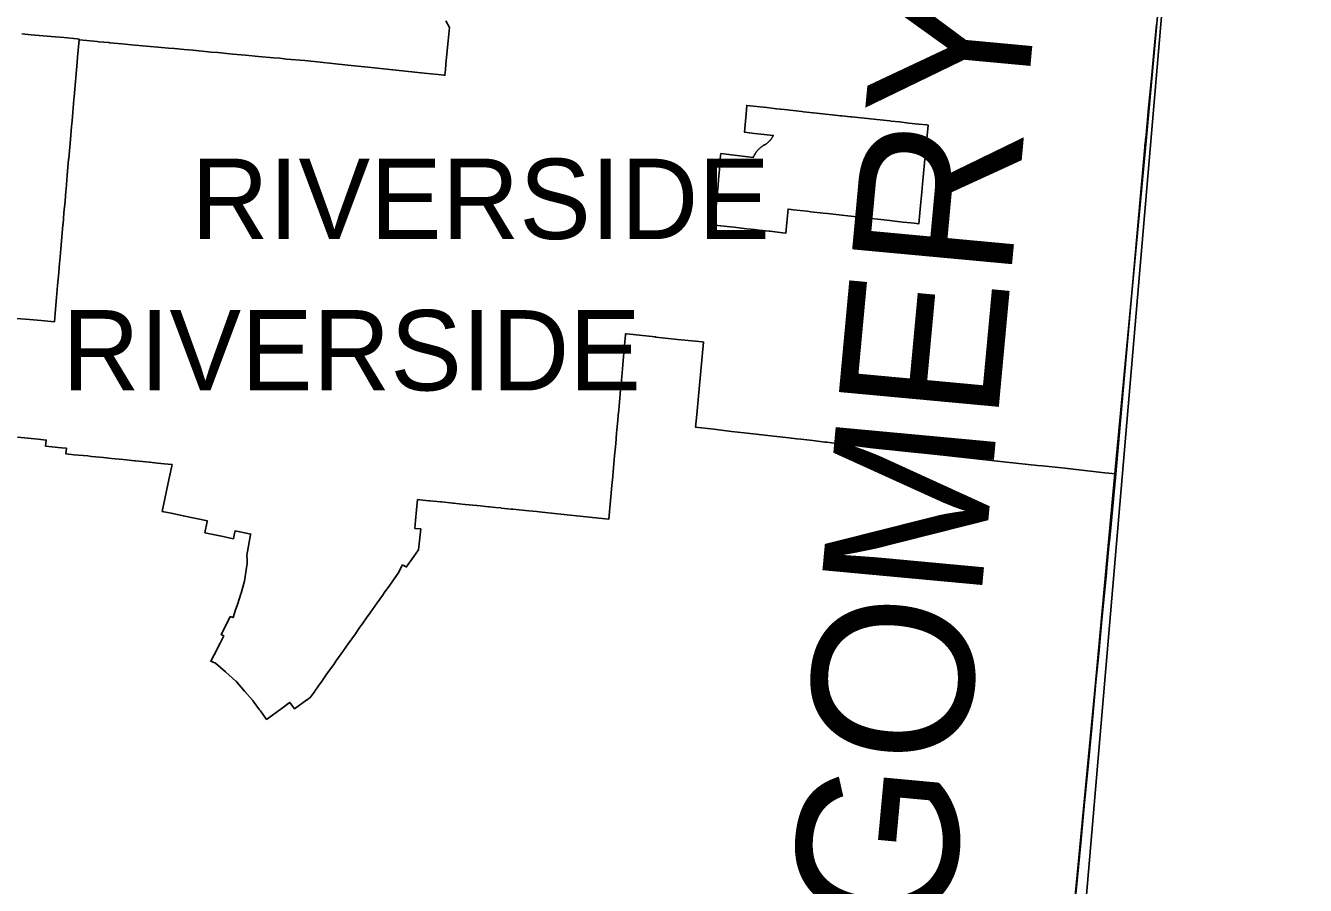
# Model space of a CAD drawing. Extents: x 0 to 34, y 0 to 22.
# Drawn here: x 5.6354 to 5.7635, y 15.4621 to 15.5481 of the extents above; entities that cross this region are included whole.
import ezdxf

# ---------------------------------------------------------------- set-up
doc = ezdxf.new("R2010")
doc.units = 0
for name, color, linetype in [('GM_X_Corporation', 7, 'Continuous'), ('GM_X_Corporation_Text', 7, 'Continuous'), ('GM_X_County', 7, 'Continuous'), ('GM_X_County_Text', 7, 'Continuous'), ('SC_Scratch1', 7, 'Continuous')]:
    doc.layers.add(name, color=color, linetype=linetype)

msp = doc.modelspace()

# ---------------------------------------------------------------- linework, layer by layer
at = {"layer": 'GM_X_Corporation'}
for points in [[(5.63452, 15.51883), (5.63582, 15.51872), (5.637, 15.51861), (5.63832, 15.51849), (5.63843, 15.51974), (5.63854, 15.52092), (5.63864, 15.52213), (5.63875, 15.52341), (5.63884, 15.5244), (5.63886, 15.52458), (5.63896, 15.52579), (5.63906, 15.52697), (5.63917, 15.52818), (5.63918, 15.52826), (5.63927, 15.52939), (5.63938, 15.53056), (5.63946, 15.53156), (5.63948, 15.53177), (5.63961, 15.53317), (5.63974, 15.53471), (5.63975, 15.53484), (5.63992, 15.53674), (5.64003, 15.53802), (5.64008, 15.5386), (5.64026, 15.54073), (5.64029, 15.54098), (5.64059, 15.54446), (5.64063, 15.54496), (5.64079, 15.5467), (5.64157, 15.54663), (5.64259, 15.54653), (5.64278, 15.54651), (5.64377, 15.54642), (5.64387, 15.54641), (5.64508, 15.5463), (5.64636, 15.54618), (5.64754, 15.54608), (5.64905, 15.54594), (5.64974, 15.54587), (5.65035, 15.54582), (5.65132, 15.54573), (5.65218, 15.54565), (5.65402, 15.54548), (5.65467, 15.54542), (5.65618, 15.54528), (5.65746, 15.54516), (5.65874, 15.54504), (5.66025, 15.5449), (5.66087, 15.54485), (5.66156, 15.54478), (5.66338, 15.54462), (5.66768, 15.54417), (5.67003, 15.54392), (5.67533, 15.54337), (5.67672, 15.54323), (5.67731, 15.54317), (5.67732, 15.54317), (5.67741, 15.54316), (5.67746, 15.54369), (5.67746, 15.54372), (5.67746, 15.54378), (5.67751, 15.5442), (5.67751, 15.54428), (5.67764, 15.54562), (5.67774, 15.54661), (5.67783, 15.54761), (5.67787, 15.54794), (5.67751, 15.5486)], [(5.74863, 15.54822), (5.74847, 15.54651), (5.74834, 15.54508), (5.74812, 15.54284), (5.74784, 15.53988), (5.74759, 15.53716), (5.74754, 15.5367), (5.74753, 15.5366), (5.74747, 15.53612), (5.74746, 15.53596), (5.74529, 15.51163), (5.74455, 15.50327), (5.74453, 15.50328), (5.74346, 15.50339), (5.73915, 15.50386), (5.73719, 15.50407), (5.73671, 15.50412), (5.73362, 15.50445), (5.73002, 15.50484), (5.72792, 15.50507), (5.72638, 15.50523), (5.72278, 15.50562), (5.72223, 15.50569), (5.71961, 15.50598), (5.71919, 15.50603), (5.71864, 15.50609), (5.71782, 15.50619), (5.71662, 15.50632), (5.71563, 15.50644), (5.71543, 15.50646), (5.71423, 15.5066), (5.71303, 15.50673), (5.71261, 15.50678), (5.7121, 15.50684), (5.71183, 15.50687), (5.71064, 15.50701), (5.70944, 15.50714), (5.70796, 15.50731), (5.70734, 15.50738), (5.7061, 15.50752), (5.70432, 15.50773), (5.7025, 15.50793), (5.70261, 15.50921), (5.70289, 15.51216), (5.70329, 15.51645), (5.70314, 15.51647), (5.70249, 15.51654), (5.70068, 15.51673), (5.69946, 15.51686), (5.69851, 15.51696), (5.69845, 15.51697), (5.69689, 15.51714), (5.69591, 15.51724), (5.69558, 15.51728), (5.69548, 15.51729), (5.69547, 15.51719), (5.69535, 15.51579), (5.69528, 15.51499), (5.69513, 15.51338), (5.6951, 15.51299), (5.6951, 15.51297), (5.69498, 15.5117), (5.69487, 15.51043), (5.6948, 15.50966), (5.69475, 15.50916), (5.69471, 15.50864), (5.69462, 15.50768), (5.69459, 15.50734), (5.6945, 15.5063), (5.69444, 15.50568), (5.69439, 15.50507), (5.69425, 15.50351), (5.69421, 15.50305), (5.6942, 15.50301), (5.69412, 15.50211), (5.69382, 15.49875), (5.69313, 15.49882), (5.68868, 15.49928), (5.68685, 15.49947), (5.6866, 15.49949), (5.6858, 15.49957), (5.6842, 15.49973), (5.68403, 15.49975), (5.68302, 15.49985), (5.683, 15.49986), (5.68246, 15.49991), (5.68185, 15.49997), (5.6818, 15.49998), (5.68064, 15.5001), (5.6806, 15.5001), (5.67943, 15.50022), (5.6794, 15.50022), (5.67826, 15.50034), (5.6782, 15.50034), (5.67708, 15.50046), (5.677, 15.50047), (5.67588, 15.50058), (5.6758, 15.50059), (5.67488, 15.50068), (5.67467, 15.5007), (5.67456, 15.49968), (5.67446, 15.49862), (5.67438, 15.49782), (5.67498, 15.49776), (5.67477, 15.49568), (5.67429, 15.495), (5.67354, 15.49394), (5.67349, 15.49397), (5.67345, 15.494), (5.6734, 15.49403), (5.67337, 15.49405), (5.67335, 15.49406), (5.6733, 15.49409), (5.67325, 15.49412), (5.67317, 15.49416), (5.67297, 15.49379), (5.6728, 15.49345), (5.67188, 15.49215), (5.67133, 15.49137), (5.67114, 15.4911), (5.67063, 15.49038), (5.6704, 15.49005), (5.66993, 15.48938), (5.66957, 15.48887), (5.66919, 15.48833), (5.66882, 15.48782), (5.66855, 15.48744), (5.66844, 15.48728), (5.66808, 15.48677), (5.66773, 15.48627), (5.66725, 15.48559), (5.66701, 15.48526), (5.6665, 15.48454), (5.66627, 15.48421), (5.66576, 15.48349), (5.66553, 15.48316), (5.66504, 15.48247), (5.66483, 15.48217), (5.66432, 15.48144), (5.66394, 15.48092), (5.6636, 15.48067), (5.66358, 15.48065), (5.66236, 15.47976), (5.66189, 15.48041), (5.66153, 15.48015), (5.66152, 15.48014), (5.66124, 15.47994), (5.65955, 15.47871), (5.65894, 15.47955), (5.65885, 15.47966), (5.65822, 15.48054), (5.65817, 15.4806), (5.65813, 15.48064), (5.65738, 15.48151), (5.65737, 15.48152), (5.65736, 15.48154), (5.65661, 15.4824), (5.65651, 15.48252), (5.65649, 15.48254), (5.65577, 15.48317), (5.65548, 15.48342), (5.65544, 15.48346), (5.65493, 15.48391), (5.65445, 15.48433), (5.65397, 15.48454), (5.6543, 15.48518), (5.6549, 15.48634), (5.65503, 15.4866), (5.65527, 15.48705), (5.65514, 15.48712), (5.65501, 15.48718), (5.65591, 15.489), (5.6562, 15.48889), (5.65645, 15.48966), (5.6566, 15.49011), (5.65687, 15.49093), (5.65698, 15.49127), (5.657, 15.49133), (5.65729, 15.49231), (5.65736, 15.49254), (5.65752, 15.49366), (5.6576, 15.49432), (5.6576, 15.49467), (5.6576, 15.49472), (5.65759, 15.49513), (5.65796, 15.49717), (5.65798, 15.49725), (5.6564, 15.49757), (5.65631, 15.49713), (5.65624, 15.49681), (5.65623, 15.49678), (5.65546, 15.49694), (5.65522, 15.49699), (5.65338, 15.49738), (5.65361, 15.49849), (5.65363, 15.49858), (5.65122, 15.49908), (5.65016, 15.49929), (5.64911, 15.49951), (5.64981, 15.50284), (5.6501, 15.5042), (5.64929, 15.50428), (5.64862, 15.50435), (5.64782, 15.50443), (5.64781, 15.50443), (5.64645, 15.50457), (5.64637, 15.50458), (5.64519, 15.5047), (5.6444, 15.50478), (5.64402, 15.50482), (5.64323, 15.5049), (5.64284, 15.50494), (5.64202, 15.50502), (5.64167, 15.50506), (5.64074, 15.50515), (5.64031, 15.50519), (5.63946, 15.50528), (5.63952, 15.50584), (5.63904, 15.50589), (5.63744, 15.50605), (5.6375, 15.50665), (5.6367, 15.50673), (5.63462, 15.50694)], [(5.67751, 15.5486), (5.67787, 15.54794), (5.67783, 15.54761), (5.67774, 15.54661), (5.67764, 15.54562), (5.67751, 15.54428), (5.67751, 15.5442), (5.67746, 15.54378), (5.67746, 15.54372), (5.67746, 15.54369), (5.67741, 15.54316), (5.67732, 15.54317), (5.67731, 15.54317), (5.67672, 15.54323), (5.67533, 15.54337), (5.67003, 15.54392), (5.66768, 15.54417), (5.66338, 15.54462), (5.66156, 15.54478), (5.66087, 15.54485), (5.66025, 15.5449), (5.65874, 15.54504), (5.65746, 15.54516), (5.65618, 15.54528), (5.65467, 15.54542), (5.65402, 15.54548), (5.65218, 15.54565), (5.65132, 15.54573), (5.65035, 15.54582), (5.64974, 15.54587), (5.64905, 15.54594), (5.64754, 15.54608), (5.64636, 15.54618), (5.64508, 15.5463), (5.64387, 15.54641), (5.64377, 15.54642), (5.64278, 15.54651), (5.64259, 15.54653), (5.64157, 15.54663), (5.64079, 15.5467), (5.64079, 15.54678), (5.6406, 15.5468), (5.6393, 15.54692), (5.63839, 15.547), (5.63599, 15.54721), (5.63505, 15.54729)], [(5.63505, 15.54729), (5.63599, 15.54721), (5.63839, 15.547), (5.6393, 15.54692), (5.6406, 15.5468), (5.64079, 15.54678), (5.64079, 15.5467), (5.64063, 15.54496), (5.64059, 15.54446), (5.64029, 15.54098), (5.6403, 15.54098), (5.64026, 15.54073), (5.64008, 15.5386), (5.64003, 15.53802), (5.63992, 15.53674), (5.63975, 15.53484), (5.63974, 15.53471), (5.63961, 15.53317), (5.63948, 15.53177), (5.63946, 15.53156), (5.63938, 15.53056), (5.63927, 15.52939), (5.63918, 15.52826), (5.63917, 15.52818), (5.63906, 15.52697), (5.63896, 15.52579), (5.63886, 15.52458), (5.63884, 15.5244), (5.63875, 15.52341), (5.63864, 15.52213), (5.63854, 15.52092), (5.63843, 15.51974), (5.63832, 15.51849), (5.637, 15.51861), (5.63582, 15.51872), (5.63452, 15.51883)], [(5.63462, 15.50694), (5.6367, 15.50673), (5.6375, 15.50665), (5.63744, 15.50605), (5.63904, 15.50589), (5.63952, 15.50584), (5.63946, 15.50528), (5.64031, 15.50519), (5.64074, 15.50515), (5.64167, 15.50506), (5.64202, 15.50502), (5.64284, 15.50494), (5.64323, 15.5049), (5.64402, 15.50482), (5.6444, 15.50478), (5.64519, 15.5047), (5.64637, 15.50458), (5.64645, 15.50457), (5.64782, 15.50443), (5.64862, 15.50435), (5.64929, 15.50428), (5.6501, 15.5042), (5.64981, 15.50284), (5.64911, 15.49951), (5.65016, 15.49929), (5.65122, 15.49908), (5.65363, 15.49858), (5.65361, 15.49849), (5.65338, 15.49738), (5.65522, 15.49699), (5.65546, 15.49694), (5.65623, 15.49678), (5.65624, 15.49681), (5.65631, 15.49713), (5.6564, 15.49757), (5.65798, 15.49725), (5.65796, 15.49717), (5.65759, 15.49513), (5.6576, 15.49472), (5.6576, 15.49467), (5.6576, 15.49432), (5.65752, 15.49366), (5.65736, 15.49254), (5.65729, 15.49231), (5.657, 15.49133), (5.65698, 15.49127), (5.65687, 15.49093), (5.6566, 15.49011), (5.65645, 15.48966), (5.6562, 15.48889), (5.65591, 15.489), (5.65501, 15.48718), (5.65514, 15.48712), (5.65527, 15.48705), (5.65503, 15.4866), (5.6549, 15.48634), (5.6543, 15.48518), (5.65397, 15.48454), (5.65445, 15.48433), (5.65493, 15.48391), (5.65544, 15.48346), (5.65548, 15.48342), (5.65577, 15.48317), (5.65649, 15.48254), (5.65651, 15.48252), (5.65661, 15.4824), (5.65736, 15.48154), (5.65738, 15.48151), (5.65813, 15.48064), (5.65817, 15.4806), (5.65822, 15.48054), (5.65885, 15.47966), (5.65894, 15.47955), (5.65955, 15.47871), (5.66124, 15.47994), (5.66152, 15.48014), (5.66189, 15.48041), (5.66236, 15.47976), (5.66358, 15.48065), (5.6636, 15.48067), (5.66394, 15.48092), (5.66432, 15.48144), (5.66483, 15.48217), (5.66504, 15.48247), (5.66553, 15.48316), (5.66576, 15.48349), (5.66627, 15.48421), (5.6665, 15.48454), (5.66701, 15.48526), (5.66725, 15.48559), (5.66773, 15.48627), (5.66808, 15.48677), (5.66844, 15.48728), (5.66855, 15.48744), (5.66882, 15.48782), (5.66919, 15.48833), (5.66957, 15.48887), (5.66993, 15.48938), (5.6704, 15.49005), (5.67063, 15.49038), (5.67114, 15.4911), (5.67133, 15.49137), (5.67188, 15.49215), (5.6728, 15.49345), (5.67297, 15.49379), (5.67317, 15.49416), (5.67325, 15.49412), (5.6733, 15.49409), (5.67335, 15.49406), (5.67337, 15.49405), (5.6734, 15.49403), (5.67345, 15.494), (5.67349, 15.49397), (5.67354, 15.49394), (5.67429, 15.495), (5.67477, 15.49568), (5.67498, 15.49776), (5.67438, 15.49782), (5.67446, 15.49862), (5.67456, 15.49968), (5.67467, 15.5007), (5.67488, 15.50068), (5.6758, 15.50059), (5.67588, 15.50058), (5.677, 15.50047), (5.67708, 15.50046), (5.6782, 15.50034), (5.67826, 15.50034), (5.6794, 15.50022), (5.67943, 15.50022), (5.6806, 15.5001), (5.68064, 15.5001), (5.6818, 15.49998), (5.68185, 15.49997), (5.68246, 15.49991), (5.683, 15.49986), (5.68302, 15.49985), (5.68403, 15.49975), (5.6842, 15.49973), (5.6858, 15.49957), (5.6866, 15.49949), (5.68685, 15.49947), (5.68868, 15.49928), (5.69313, 15.49882), (5.69382, 15.49875), (5.69412, 15.50211), (5.6942, 15.50301), (5.69421, 15.50305), (5.69425, 15.50351), (5.69439, 15.50507), (5.69444, 15.50568), (5.6945, 15.5063), (5.69459, 15.50734), (5.69462, 15.50768), (5.69471, 15.50864), (5.69475, 15.50916), (5.6948, 15.50966), (5.69487, 15.51043), (5.69498, 15.5117), (5.6951, 15.51297), (5.6951, 15.51299), (5.69513, 15.51338), (5.69528, 15.51499), (5.69535, 15.51579), (5.69547, 15.51719), (5.69548, 15.51729), (5.69558, 15.51728), (5.69591, 15.51724), (5.69689, 15.51714), (5.69845, 15.51697), (5.69851, 15.51696), (5.69946, 15.51686), (5.70068, 15.51673), (5.70249, 15.51654), (5.70314, 15.51647), (5.70329, 15.51645), (5.70289, 15.51216), (5.70261, 15.50921), (5.7025, 15.50793), (5.70432, 15.50773), (5.7061, 15.50752), (5.70734, 15.50738), (5.70796, 15.50731), (5.70944, 15.50714), (5.71064, 15.50701), (5.71183, 15.50687), (5.7121, 15.50684), (5.71261, 15.50678), (5.71303, 15.50673), (5.71423, 15.5066), (5.71543, 15.50646), (5.71563, 15.50644), (5.71662, 15.50632), (5.71782, 15.50619), (5.71864, 15.50609), (5.71919, 15.50603), (5.71961, 15.50598), (5.72223, 15.50569), (5.72278, 15.50562), (5.72638, 15.50523), (5.72792, 15.50507), (5.73002, 15.50484), (5.73362, 15.50445), (5.73671, 15.50412), (5.73719, 15.50407), (5.73915, 15.50386), (5.74346, 15.50339), (5.74455, 15.50327), (5.74394, 15.49684), (5.74386, 15.49606), (5.74365, 15.49386), (5.74361, 15.49338), (5.74322, 15.48934), (5.74313, 15.48834), (5.74284, 15.48531), (5.74278, 15.48464), (5.7426, 15.48275), (5.74253, 15.48205), (5.74246, 15.4813), (5.74214, 15.4779), (5.74174, 15.47368), (5.74139, 15.47003), (5.74104, 15.46634), (5.74068, 15.46258), (5.74033, 15.45891)]]:
    msp.add_lwpolyline(points, dxfattribs=at)
for points in [[(5.70739, 15.53745), (5.70755, 15.53929), (5.70762, 15.54014), (5.70861, 15.54003), (5.70961, 15.53992), (5.7106, 15.53981), (5.71097, 15.53977), (5.7114, 15.53972), (5.71313, 15.53953), (5.7133, 15.53951), (5.71426, 15.53941), (5.71522, 15.5393), (5.7155, 15.53927), (5.71617, 15.5392), (5.71699, 15.53911), (5.71713, 15.53909), (5.718, 15.539), (5.71809, 15.53899), (5.71905, 15.53889), (5.72001, 15.53878), (5.72097, 15.53868), (5.72193, 15.53858), (5.72207, 15.53856), (5.72289, 15.53848), (5.72385, 15.53837), (5.72481, 15.53827), (5.72565, 15.53818), (5.72577, 15.53817), (5.72551, 15.53547), (5.72521, 15.53225), (5.72513, 15.53145), (5.72501, 15.53011), (5.72484, 15.52829), (5.72436, 15.52834), (5.72404, 15.52838), (5.72324, 15.52846), (5.72218, 15.52858), (5.72192, 15.52861), (5.72164, 15.52864), (5.72072, 15.52875), (5.72004, 15.52882), (5.71953, 15.52888), (5.71845, 15.529), (5.71833, 15.52902), (5.71713, 15.52915), (5.71685, 15.52918), (5.71569, 15.52931), (5.71525, 15.52936), (5.71402, 15.5295), (5.71365, 15.52954), (5.71226, 15.5297), (5.71206, 15.52972), (5.71175, 15.52976), (5.71163, 15.52841), (5.71153, 15.52736), (5.71121, 15.52739), (5.70993, 15.52754), (5.70986, 15.52754), (5.70885, 15.52766), (5.70838, 15.52771), (5.70802, 15.52775), (5.70758, 15.5278), (5.70637, 15.52794), (5.70598, 15.52798), (5.70439, 15.52816), (5.70447, 15.52914), (5.70458, 15.53034), (5.70461, 15.53056), (5.70468, 15.53146), (5.70474, 15.53215), (5.70479, 15.53274), (5.70488, 15.53373), (5.7049, 15.53394), (5.705, 15.53514), (5.70502, 15.53531), (5.70827, 15.53494), (5.7083, 15.53502), (5.70832, 15.53505), (5.70834, 15.53509), (5.70836, 15.53513), (5.70838, 15.53517), (5.7084, 15.5352), (5.70842, 15.53524), (5.70844, 15.53528), (5.70846, 15.53531), (5.70848, 15.53535), (5.70851, 15.53538), (5.70853, 15.53542), (5.70855, 15.53545), (5.70858, 15.53549), (5.7086, 15.53552), (5.70863, 15.53555), (5.70866, 15.53559), (5.70868, 15.53562), (5.70871, 15.53565), (5.70874, 15.53568), (5.70877, 15.53571), (5.7088, 15.53574), (5.70883, 15.53577), (5.70886, 15.5358), (5.70889, 15.53583), (5.70892, 15.53586), (5.70895, 15.53589), (5.70899, 15.53591), (5.70902, 15.53594), (5.70905, 15.53597), (5.70908, 15.53599), (5.70912, 15.53601), (5.70915, 15.53604), (5.70919, 15.53606), (5.70922, 15.53609), (5.70926, 15.53611), (5.7093, 15.53613), (5.70933, 15.53615), (5.7094, 15.53619), (5.70943, 15.5362), (5.70946, 15.53622), (5.70949, 15.53624), (5.70952, 15.53626), (5.70955, 15.53628), (5.70958, 15.5363), (5.70961, 15.53632), (5.70963, 15.53634), (5.70966, 15.53636), (5.70969, 15.53638), (5.70972, 15.53641), (5.70974, 15.53643), (5.70977, 15.53645), (5.70979, 15.53648), (5.70982, 15.5365), (5.70984, 15.53653), (5.70987, 15.53655), (5.70989, 15.53658), (5.70992, 15.5366), (5.70994, 15.53663), (5.70996, 15.53666), (5.70998, 15.53668), (5.71001, 15.53671), (5.71003, 15.53674), (5.71005, 15.53677), (5.71007, 15.5368), (5.71009, 15.53682), (5.71011, 15.53685), (5.71013, 15.53688), (5.71014, 15.53691), (5.71016, 15.53694), (5.71018, 15.53697), (5.7102, 15.53701), (5.71021, 15.53704), (5.71023, 15.53707), (5.71025, 15.53712), (5.71026, 15.53713), (5.70937, 15.53723), (5.70838, 15.53734)], [(5.71153, 15.52736), (5.71163, 15.52841), (5.71175, 15.52976), (5.71206, 15.52972), (5.71226, 15.5297), (5.71365, 15.52954), (5.71402, 15.5295), (5.71525, 15.52936), (5.71569, 15.52931), (5.71685, 15.52918), (5.71713, 15.52915), (5.71833, 15.52902), (5.71845, 15.529), (5.71953, 15.52888), (5.72004, 15.52882), (5.72072, 15.52875), (5.72164, 15.52864), (5.72192, 15.52861), (5.72218, 15.52858), (5.72324, 15.52846), (5.72404, 15.52838), (5.72436, 15.52834), (5.72484, 15.52829), (5.72501, 15.53011), (5.72513, 15.53145), (5.72521, 15.53225), (5.72551, 15.53547), (5.72577, 15.53817), (5.72565, 15.53818), (5.72481, 15.53827), (5.72385, 15.53837), (5.72289, 15.53848), (5.72207, 15.53856), (5.72193, 15.53858), (5.72097, 15.53868), (5.72001, 15.53878), (5.71905, 15.53889), (5.71809, 15.53899), (5.718, 15.539), (5.71713, 15.53909), (5.71699, 15.53911), (5.71617, 15.5392), (5.7155, 15.53927), (5.71522, 15.5393), (5.71426, 15.53941), (5.7133, 15.53951), (5.71313, 15.53953), (5.7114, 15.53972), (5.711, 15.53977), (5.71097, 15.53977), (5.7106, 15.53981), (5.70961, 15.53992), (5.70861, 15.54003), (5.70762, 15.54014), (5.70755, 15.53929), (5.70739, 15.53745), (5.70838, 15.53734), (5.70937, 15.53723), (5.71026, 15.53713), (5.71025, 15.53712), (5.71023, 15.53707), (5.71021, 15.53704), (5.7102, 15.53701), (5.71018, 15.53697), (5.71016, 15.53694), (5.71014, 15.53691), (5.71013, 15.53688), (5.71011, 15.53685), (5.71009, 15.53682), (5.71007, 15.5368), (5.71005, 15.53677), (5.71003, 15.53674), (5.71001, 15.53671), (5.70998, 15.53668), (5.70996, 15.53666), (5.70994, 15.53663), (5.70992, 15.5366), (5.70989, 15.53658), (5.70987, 15.53655), (5.70984, 15.53653), (5.70982, 15.5365), (5.70979, 15.53648), (5.70977, 15.53645), (5.70974, 15.53643), (5.70972, 15.53641), (5.70969, 15.53638), (5.70966, 15.53636), (5.70963, 15.53634), (5.70961, 15.53632), (5.70958, 15.5363), (5.70955, 15.53628), (5.70952, 15.53626), (5.70949, 15.53624), (5.70946, 15.53622), (5.70943, 15.5362), (5.7094, 15.53619), (5.70933, 15.53615), (5.7093, 15.53613), (5.70926, 15.53611), (5.70922, 15.53609), (5.70919, 15.53606), (5.70915, 15.53604), (5.70912, 15.53601), (5.70908, 15.53599), (5.70905, 15.53597), (5.70902, 15.53594), (5.70899, 15.53591), (5.70895, 15.53589), (5.70892, 15.53586), (5.70889, 15.53583), (5.70886, 15.5358), (5.70883, 15.53577), (5.7088, 15.53574), (5.70877, 15.53571), (5.70874, 15.53568), (5.70871, 15.53565), (5.70868, 15.53562), (5.70866, 15.53559), (5.70863, 15.53555), (5.7086, 15.53552), (5.70858, 15.53549), (5.70855, 15.53545), (5.70853, 15.53542), (5.70851, 15.53538), (5.70848, 15.53535), (5.70846, 15.53531), (5.70844, 15.53528), (5.70842, 15.53524), (5.7084, 15.5352), (5.70838, 15.53517), (5.70836, 15.53513), (5.70834, 15.53509), (5.70832, 15.53505), (5.7083, 15.53502), (5.70827, 15.53494), (5.70502, 15.53531), (5.705, 15.53514), (5.7049, 15.53394), (5.70488, 15.53373), (5.70479, 15.53274), (5.70474, 15.53215), (5.70468, 15.53146), (5.70461, 15.53056), (5.70458, 15.53034), (5.70447, 15.52914), (5.70439, 15.52816), (5.70598, 15.52798), (5.70637, 15.52794), (5.70758, 15.5278), (5.70802, 15.52775), (5.70838, 15.52771), (5.70885, 15.52766), (5.70986, 15.52754), (5.70993, 15.52754), (5.71121, 15.52739)]]:
    msp.add_lwpolyline(points, close=True, dxfattribs=at)
at = {"layer": 'GM_X_County'}
msp.add_lwpolyline([(5.76379, 15.62102), (5.76033, 15.62135), (5.75621, 15.62175), (5.75534, 15.62182), (5.74758, 15.5366), (5.74443, 15.50293), (5.74247, 15.48198), (5.73958, 15.45162)], dxfattribs=at)
at = {"layer": 'SC_Scratch1'}
msp.add_lwpolyline([(6.84427, 15.52102), (6.47407, 15.55166), (6.43886, 15.55469), (6.44702, 15.64199), (6.28415, 15.65664), (6.13316, 15.67088), (5.99067, 15.68499), (5.93347, 15.69052), (5.92502, 15.60599), (5.90267, 15.60794), (5.90147, 15.60838), (5.80287, 15.61779), (5.75534, 15.62182), (5.73004, 15.32562), (5.72924, 15.29101), (5.72839, 15.28607), (5.72592, 15.27969), (5.7131, 15.14518), (5.68829, 14.88472), (5.67064, 14.67069)], dxfattribs=at)

# ---------------------------------------------------------------- texts
at = {"layer": 'GM_X_Corporation_Text'}
for p in [(5.652, 15.52677), (5.63909, 15.51162)]:
    msp.add_text('RIVERSIDE', height=0.008037, rotation=0, dxfattribs=at).set_placement(p)
at = {"layer": 'GM_X_County_Text'}
msp.add_text('MONTGOMERY COUNTY', height=0.016074, rotation=84.7018, dxfattribs=at).set_placement((5.7221, 15.39409))

doc.saveas('drawing.dxf')
